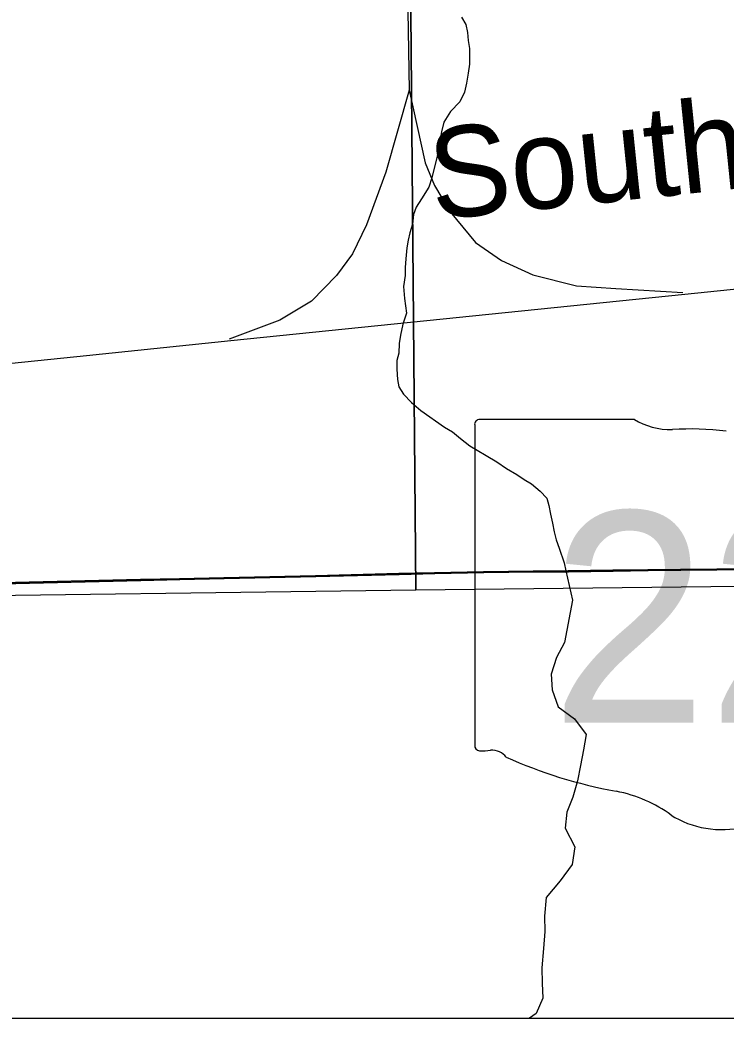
# Model space of a CAD drawing. Extents: x 0 to 34, y 0 to 22.
# Drawn here: x 5.258 to 5.699, y 14.1 to 14.723 of the extents above; entities that cross this region are included whole.
import ezdxf

# ---------------------------------------------------------------- set-up
doc = ezdxf.new("R2010")
doc.units = 0
for name, color, linetype in [('Default', 7, 'Continuous'), ('GM_X_Minor_River', 7, 'Continuous'), ('GM_X_Rail_Line', 7, 'Continuous'), ('GM_X_Rail_Line_Text', 7, 'Continuous'), ('GM_X_Section', 7, 'Continuous'), ('GM_X_State_Location', 7, 'Continuous'), ('GM_X_State_Route', 7, 'Continuous'), ('GM_X_State_Shield', 7, 'Continuous'), ('SH_Cut_Line', 7, 'Continuous'), ('SH_Data', 7, 'Continuous')]:
    doc.layers.add(name, color=color, linetype=linetype)

msp = doc.modelspace()

# ---------------------------------------------------------------- linework, layer by layer
at = {"layer": 'Default'}
for points in [[(5.24637, 14.37175), (5.33336, 14.37384), (5.35769, 14.37435), (5.38536, 14.37496), (5.44266, 14.37623), (5.49469, 14.37751), (5.51706, 14.37807), (5.54764, 14.37868), (5.57871, 14.37911), (5.60046, 14.37925), (5.6284, 14.37963), (5.65019, 14.3799), (5.67058, 14.38019), (5.71576, 14.3806)], [(5.71576, 14.3806), (5.67058, 14.38019), (5.65019, 14.3799), (5.6284, 14.37963), (5.60046, 14.37925), (5.57871, 14.37911), (5.54764, 14.37868), (5.51706, 14.37807), (5.49469, 14.37751), (5.44266, 14.37623), (5.38536, 14.37496), (5.35769, 14.37435), (5.33336, 14.37384), (5.24637, 14.37175)], [(3.68028, 14.09996), (8.9, 14.09996)]]:
    msp.add_lwpolyline(points, dxfattribs=at)
at = {"layer": 'GM_X_Minor_River'}
for points in [[(5.53379, 14.72497), (5.53647, 14.72041), (5.53762, 14.71546), (5.53802, 14.71052), (5.53879, 14.70557), (5.53881, 14.69569), (5.53807, 14.68998), (5.53694, 14.6839), (5.5358, 14.6782), (5.53276, 14.67212), (5.52705, 14.66604), (5.52287, 14.65957), (5.52136, 14.65349), (5.52061, 14.64893), (5.51948, 14.64246), (5.51834, 14.63714), (5.51683, 14.63068), (5.51532, 14.6246), (5.51343, 14.61889), (5.50886, 14.61167), (5.50544, 14.60635), (5.50393, 14.60179), (5.50318, 14.59571), (5.50166, 14.59038), (5.50053, 14.58582), (5.49978, 14.58088), (5.49903, 14.57403), (5.49866, 14.56871), (5.49867, 14.56377), (5.49754, 14.55693), (5.49832, 14.54932), (5.49949, 14.54019), (5.49722, 14.53335), (5.49571, 14.52651), (5.49496, 14.52119), (5.49459, 14.5151), (5.49345, 14.51054), (5.49347, 14.50522), (5.49386, 14.49875)], [(5.49386, 14.49875), (5.49464, 14.49419), (5.4977, 14.48962), (5.50267, 14.4843), (5.50841, 14.47935), (5.52332, 14.46907), (5.52829, 14.46603), (5.53326, 14.46184), (5.53899, 14.45728), (5.54358, 14.45461), (5.54931, 14.45119), (5.55581, 14.44738), (5.56193, 14.4432), (5.56842, 14.43939), (5.57301, 14.43634), (5.5776, 14.43368), (5.58295, 14.42911), (5.58716, 14.42455), (5.58831, 14.41998), (5.58947, 14.41466), (5.59063, 14.40896), (5.59179, 14.40363), (5.59294, 14.39869), (5.59486, 14.39336), (5.59794, 14.38424), (5.59909, 14.37929), (5.60325, 14.36086)], [(5.60325, 14.36086), (5.59812, 14.33459), (5.59327, 14.32508), (5.58993, 14.31482), (5.59038, 14.30497), (5.59425, 14.29437), (5.60453, 14.28685), (5.6118, 14.27704), (5.60998, 14.26755), (5.60815, 14.25768), (5.60633, 14.24819), (5.60337, 14.23793), (5.59965, 14.22843), (5.59859, 14.21856), (5.60473, 14.20685), (5.60292, 14.19584), (5.59542, 14.18556), (5.58678, 14.17527), (5.58573, 14.16351), (5.5858, 14.15403), (5.58512, 14.14341), (5.58407, 14.13127), (5.58414, 14.12179), (5.58459, 14.11231), (5.58049, 14.10281), (5.57635, 14.09996)]]:
    msp.add_lwpolyline(points, dxfattribs=at)
at = {"layer": 'GM_X_Rail_Line'}
for points in [[(5.88863, 16.83347), (5.72006, 16.39003), (5.49797, 15.81639), (5.48598, 15.77743), (5.48054, 15.734), (5.48036, 15.69941), (5.49584, 14.98866), (5.50116, 14.67953)], [(5.50116, 14.67953), (5.48651, 14.62826), (5.47453, 14.59529), (5.46572, 14.57733), (5.45582, 14.56362), (5.4402, 14.54762), (5.42039, 14.53581), (5.38866, 14.52388)], [(5.50116, 14.67953), (5.51115, 14.63403), (5.517, 14.61986), (5.52668, 14.60343), (5.54265, 14.58431), (5.55885, 14.57306), (5.57842, 14.56406), (5.60565, 14.55731), (5.63029, 14.55552), (5.67218, 14.55309)], [(5.11889, 14.49521), (5.29962, 14.51377), (5.38966, 14.52305), (5.6733, 14.55209), (5.92816, 14.57822), (6.17334, 14.60341), (6.43245, 14.62993), (6.5087, 14.63828), (6.53018, 14.6412), (6.54711, 14.6439), (6.56184, 14.64656), (6.57733, 14.64967), (6.59274, 14.65332), (6.60952, 14.65764), (6.62645, 14.66273)]]:
    msp.add_lwpolyline(points, dxfattribs=at)
at = {"layer": 'GM_X_Section'}
for points in [[(5.49662, 15.37719), (6.00137, 15.38987), (6.50804, 15.39727), (6.51868, 14.37863), (5.50533, 14.36709)], [(4.46211, 15.35397), (5.37649, 15.3766), (5.49662, 15.37719), (5.50533, 14.36709), (4.47378, 14.3535)]]:
    msp.add_lwpolyline(points, close=True, dxfattribs=at)
at = {"layer": 'GM_X_State_Route'}
msp.add_lwpolyline([(5.24658, 14.37121), (5.33357, 14.37329), (5.3579, 14.3738), (5.38557, 14.37442), (5.44287, 14.37569), (5.4949, 14.37696), (5.51727, 14.37753), (5.54786, 14.37814), (5.57892, 14.37857), (5.60067, 14.3787), (5.62862, 14.37909), (5.6504, 14.37936), (5.67079, 14.37964), (5.71597, 14.38006)], dxfattribs=at)
at = {"layer": 'GM_X_State_Shield'}
for p, q in [((5.54209, 14.4704), (5.54209, 14.27028)), ((5.64186, 14.47385), (5.54534, 14.47385))]:
    msp.add_line(p, q, dxfattribs=at)
for centre, major_axis, start_param, end_param in [((5.54587, 14.47083), (0.00382, 0), 1.712693, 3.28349), ((5.66484, 14.49708), (0.03703, 0), 4.042523, 4.731795), ((5.67712, 14.3615), (0.13295, 0), 1.404758, 1.657858), ((5.5459, 14.26985), (0.00385, 0), 3.00124, 4.508301), ((5.54649, 14.29032), (0.0294, 0), 4.665946, 4.897461), ((5.5525, 14.25874), (0.0106, 0), 0.519207, 1.627899), ((5.68633, 14.43854), (0.2524, 0), 4.195997, 4.488961), ((5.61108, 14.18038), (0.07897, 0), 0.823519, 1.323587), ((5.69649, 14.25775), (0.05011, 0), 4.026481, 4.996735)]:
    msp.add_ellipse(centre, major_axis=major_axis, ratio=0.8, start_param=start_param, end_param=end_param, dxfattribs=at)
at = {"layer": 'SH_Cut_Line'}
for points in [[(5.71576, 14.3806), (5.67058, 14.38019), (5.65019, 14.3799), (5.6284, 14.37963), (5.60046, 14.37925), (5.57871, 14.37911), (5.54764, 14.37868), (5.51706, 14.37807), (5.49469, 14.37751), (5.44266, 14.37623), (5.38536, 14.37496), (5.35769, 14.37435), (5.33336, 14.37384), (5.24637, 14.37175)], [(5.24637, 14.37175), (5.33336, 14.37384), (5.35769, 14.37435), (5.38536, 14.37496), (5.44266, 14.37623), (5.49469, 14.37751), (5.51706, 14.37807), (5.54764, 14.37868), (5.57871, 14.37911), (5.60046, 14.37925), (5.6284, 14.37963), (5.65019, 14.3799), (5.67058, 14.38019), (5.71576, 14.3806)], [(2.1, 14.09996), (8.9, 14.09996)]]:
    msp.add_lwpolyline(points, dxfattribs=at)
at = {"layer": 'SH_Data'}
msp.add_line((2.1, 14.09996), (8.9, 14.09996), dxfattribs=at)

# ---------------------------------------------------------------- texts
at = {"layer": 'GM_X_Rail_Line_Text'}
msp.add_text('Southern', height=0.056629, rotation=5.86699, dxfattribs=at).set_placement((5.51664, 14.59844))
at = {"layer": 'GM_X_State_Location'}
msp.add_text('226', height=0.000189, rotation=0.00001, dxfattribs=at).set_placement((5.63632, 14.34326))
at = {"layer": 'GM_X_State_Shield'}
msp.add_text('226', height=0.131836, dxfattribs=at).set_placement((5.58952, 14.2844))

doc.saveas('drawing.dxf')
